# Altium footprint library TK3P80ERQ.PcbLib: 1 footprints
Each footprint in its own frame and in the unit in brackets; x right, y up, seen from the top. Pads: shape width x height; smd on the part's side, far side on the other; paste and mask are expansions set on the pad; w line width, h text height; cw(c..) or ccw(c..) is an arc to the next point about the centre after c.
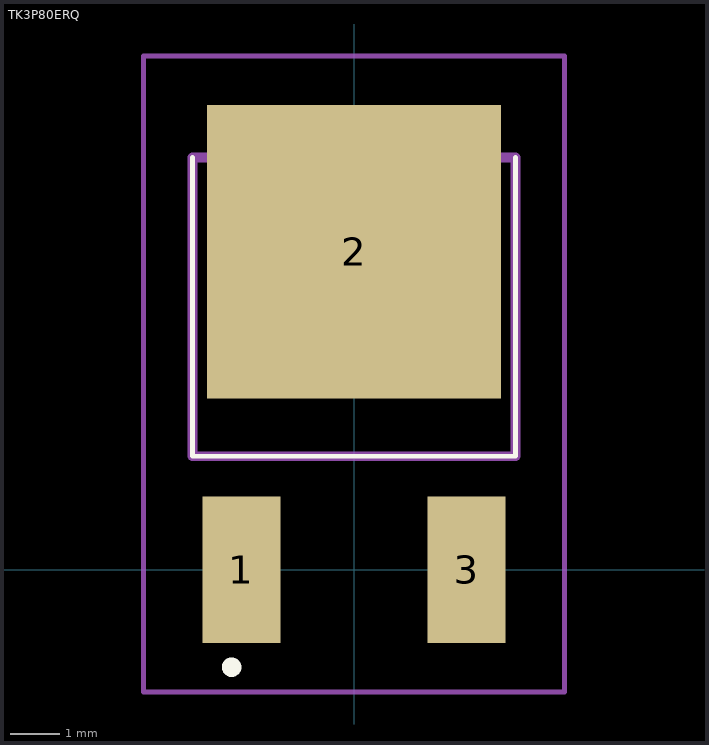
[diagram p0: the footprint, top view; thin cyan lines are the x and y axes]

## TK3P80ERQ [mm]
pads (3):
  rect 1.6x3 smd: 1(-2.3,0) 3(2.3,0)
  rect 6x6 smd: 2(0,6.5)
Top Overlay:
  lines w0.1: -3.3,8.42 -3.3,2.32 3.3,2.32 3.3,8.42
  lines w0.2: -2.6,-1.99 cw(c-2.5,-1.99) -2.4,-1.99 ; -2.6,-1.99 -2.6,-1.99 ; -2.6,-1.99 ccw(c-2.5,-1.99) -2.4,-1.99 ; -2.4,-1.99 -2.4,-1.99
Mechanical 15:
  lines w0.2: -3.3,2.32 3.3,2.32 3.3,8.42 -3.3,8.42 -3.3,2.32
Mechanical 20:
  lines w0.1: -4.3,-2.5 4.3,-2.5 4.3,10.5 -4.3,10.5 -4.3,-2.5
